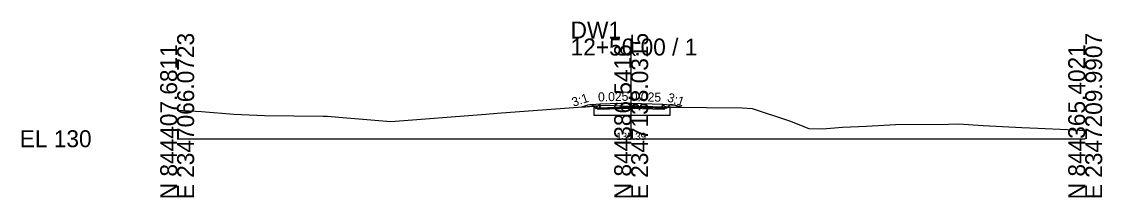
# Model space of a CAD drawing. Extents: x -26 to 2347152, y 490 to 844394.
# Drawn here: x -25.7 to 152.8, y 2490.3 to 2519.3 of the extents above; entities that cross this region are included whole.
import ezdxf

# ---------------------------------------------------------------- set-up
doc = ezdxf.new("R2010")
doc.units = 0
for name, color, linetype in [('Exist Cross Section Cell', 7, 'Continuous'), ('Exist XS Center Line Elevation Label', 7, 'Continuous'), ('Exist XS Ground Line', 7, 'Continuous'), ('Prop CMT Pvmt Course 1', 7, 'Continuous'), ('Prop CMT Pvmt Surface', 7, 'Continuous'), ('Prop CMT Pvmt Surface Shoulder', 7, 'Continuous'), ('Prop CMT Shld Paved Course 1', 7, 'Continuous'), ('Prop CMT Slope Grass', 7, 'Continuous'), ('Prop CMT Subgrade Earthwork', 7, 'Continuous'), ('Prop Road Sect_ Recs - UC Shallow (Outline)', 7, 'Continuous'), ('Prop Road Sect_ Recs - UC Shallow (Pattern)', 7, 'Continuous'), ('Prop XS Earthwork Shape', 7, 'Continuous'), ('Prop XS SE Text', 7, 'Continuous'), ('Prop XS Side Slope Text', 7, 'Continuous')]:
    doc.layers.add(name, color=color, linetype=linetype)

msp = doc.modelspace()

# ---------------------------------------------------------------- linework, layer by layer
at = {"layer": 'Exist Cross Section Cell'}
for p, q in [((75, 2500), (75, 2516.55)), ((0, 2500), (75, 2500)), ((75, 2500), (150, 2500))]:
    msp.add_line(p, q, dxfattribs=at)
at = {"layer": 'Exist XS Ground Line'}
msp.add_lwpolyline([(0, 2504.69), (4.02, 2504.49), (9.34, 2504.03), (14.44, 2503.82), (24.1, 2503.72), (24.86, 2503.71), (26.7, 2503.55), (35.29, 2502.82), (50.97, 2504.04), (52.88, 2504.2), (53.56, 2504.25), (70.72, 2505.52), (75, 2505.39), (76.76, 2505.34), (78.58, 2505.33), (81.53, 2505.23), (93.33, 2505.11), (95, 2504.98), (101.16, 2502.98), (104.35, 2501.71), (106.63, 2501.65), (109.91, 2501.9), (113.9, 2502.07), (118.67, 2502.36), (127.41, 2502.43), (129.09, 2502.45), (133.14, 2502.18), (139.52, 2501.84), (142.17, 2501.75), (147.06, 2501.53), (150, 2501.35)], dxfattribs=at)
at = {"layer": 'Prop CMT Pvmt Course 1'}
for p, q in [((75, 2505.86), (69.8, 2505.73)), ((69.8, 2505.73), (69.8, 2505.48)), ((69.8, 2505.06), (75.01, 2505.19)), ((69.8, 2505.06), (75.01, 2505.19)), ((80.2, 2505.06), (74.98, 2505.19)), ((80.2, 2505.06), (74.98, 2505.19)), ((75, 2505.61), (75, 2505.86)), ((75, 2505.86), (80.2, 2505.73)), ((75, 2505.61), (75, 2505.86)), ((75, 2505.61), (75, 2505.73)), ((75, 2505.73), (75, 2505.73)), ((75, 2505.73), (75, 2505.61)), ((75, 2505.61), (75, 2505.73)), ((75, 2505.73), (75, 2505.73)), ((75, 2505.73), (75, 2505.61)), ((75, 2505.61), (75, 2505.61)), ((75, 2505.61), (75, 2505.61)), ((80.2, 2505.73), (80.2, 2505.48))]:
    msp.add_line(p, q, dxfattribs=at)
for points in [[(75, 2505.86), (69.8, 2505.73)], [(69.8, 2505.73), (69.8, 2505.06)], [(75, 2505.61), (75, 2505.86)], [(75, 2505.86), (80.2, 2505.73)], [(75, 2505.19), (75, 2505.86)], [(80.2, 2505.73), (80.2, 2505.06)]]:
    msp.add_lwpolyline(points, dxfattribs=at)
msp.add_lwpolyline([(75, 2505.61), (75, 2505.73), (75, 2505.73), (75, 2505.61)], close=True, dxfattribs=at)
msp.add_lwpolyline([(75, 2505.61), (75, 2505.73), (75, 2505.73), (75, 2505.61)], close=True, dxfattribs=at)
at = {"layer": 'Prop CMT Pvmt Surface'}
for q in [(69.8, 2505.73), (80.2, 2505.73)]:
    msp.add_line((75, 2505.86), q, dxfattribs=at)
for points in [[(75, 2505.86), (69.8, 2505.73)], [(75, 2505.86), (80.2, 2505.73)]]:
    msp.add_lwpolyline(points, dxfattribs=at)
at = {"layer": 'Prop CMT Pvmt Surface Shoulder'}
for p, q in [((69.8, 2505.73), (69.8, 2505.73)), ((80.2, 2505.73), (80.2, 2505.73))]:
    msp.add_line(p, q, dxfattribs=at)
for points in [[(69.8, 2505.73), (69.8, 2505.73)], [(80.2, 2505.73), (80.2, 2505.73)]]:
    msp.add_lwpolyline(points, dxfattribs=at)
at = {"layer": 'Prop CMT Shld Paved Course 1'}
for p, q in [((69.8, 2505.73), (69.12, 2505.05)), ((69.54, 2505.05), (69.8, 2505.06)), ((69.8, 2505.73), (69.8, 2505.73)), ((69.8, 2505.48), (69.8, 2505.73)), ((80.2, 2505.73), (80.2, 2505.73)), ((80.2, 2505.73), (80.88, 2505.05)), ((80.2, 2505.48), (80.2, 2505.73)), ((80.46, 2505.05), (80.2, 2505.06))]:
    msp.add_line(p, q, dxfattribs=at)
for points in [[(69.8, 2505.73), (69.12, 2505.05)], [(69.12, 2505.05), (69.8, 2505.06)], [(69.8, 2505.73), (69.8, 2505.73)], [(69.8, 2505.06), (69.8, 2505.73)], [(80.2, 2505.73), (80.2, 2505.73)], [(80.2, 2505.73), (80.88, 2505.05)], [(80.2, 2505.06), (80.2, 2505.73)], [(80.88, 2505.05), (80.2, 2505.06)]]:
    msp.add_lwpolyline(points, dxfattribs=at)
at = {"layer": 'Prop CMT Slope Grass'}
for p, q in [((67.8, 2505.57), (66.77, 2505.22)), ((69.8, 2505.73), (67.8, 2505.57)), ((80.2, 2505.73), (82.2, 2505.57)), ((82.2, 2505.57), (83.26, 2505.21))]:
    msp.add_line(p, q, dxfattribs=at)
at = {"layer": 'Prop CMT Subgrade Earthwork'}
for p, q in [((68.54, 2505.63), (69.12, 2505.05)), ((81.46, 2505.63), (80.88, 2505.05))]:
    msp.add_line(p, q, dxfattribs=at)
for points in [[(75.01, 2505.19), (69.12, 2505.05)], [(75.01, 2505.19), (80.88, 2505.05)]]:
    msp.add_lwpolyline(points, dxfattribs=at)
at = {"layer": 'Prop Road Sect_ Recs - UC Shallow (Outline)'}
for p, q in [((69.16, 2505.4), (68.82, 2505.38)), ((68.82, 2505.38), (68.82, 2503.88)), ((69.61, 2504.85), (69.16, 2505.4)), ((75, 2504.98), (69.61, 2504.85)), ((75.01, 2504.98), (71, 2504.88)), ((80.39, 2504.85), (75, 2504.98)), ((80.72, 2505.26), (80.39, 2504.85)), ((81.42, 2505.23), (80.72, 2505.26)), ((81.43, 2503.88), (81.42, 2505.23)), ((68.82, 2503.88), (81.43, 2503.88))]:
    msp.add_line(p, q, dxfattribs=at)
at = {"layer": 'Prop Road Sect_ Recs - UC Shallow (Pattern)'}
msp.add_lwpolyline([(68.82, 2505.38), (68.82, 2503.88), (81.43, 2503.88), (81.42, 2505.23), (80.72, 2505.26), (80.39, 2504.85), (75, 2504.98), (69.61, 2504.85), (69.16, 2505.4), (68.82, 2505.38)], dxfattribs=at)
msp.add_lwpolyline([(68.82, 2505.38), (68.82, 2503.88), (81.43, 2503.88), (81.42, 2505.23), (80.72, 2505.26), (80.39, 2504.85), (75, 2504.98), (69.61, 2504.85), (69.16, 2505.4), (68.82, 2505.38)], dxfattribs=at)
at = {"layer": 'Prop XS Earthwork Shape'}
for points in [[(68.54, 2505.63), (67.8, 2505.57), (66.77, 2505.22), (68.79, 2505.37)], [(81.08, 2505.24), (80.88, 2505.05), (75.01, 2505.19), (69.12, 2505.05), (68.79, 2505.37), (70.72, 2505.52), (75, 2505.39), (76.76, 2505.34), (78.58, 2505.33)], [(81.08, 2505.24), (81.53, 2505.23), (83.26, 2505.21), (82.2, 2505.57), (81.46, 2505.63)]]:
    msp.add_lwpolyline(points, close=True, dxfattribs=at)

# ---------------------------------------------------------------- texts
at = {"layer": 'Exist Cross Section Cell'}
for s, p in [('DW1', (65, 2516.55)), ('12+50.00 / 1', (65, 2513.75)), ('EL 130', (-26, 2498.6))]:
    msp.add_text(s, height=2.8, dxfattribs=at).set_placement(p)
for s, p in [('E 2347066.0723', (2.8, 2490)), ('E 2347138.0315', (77.8, 2490)), ('E 2347209.9907', (152.8, 2490)), ('N 844407.6811', (0, 2490)), ('N 844386.5416', (75, 2490)), ('N 844365.4021', (150, 2490))]:
    msp.add_text(s, height=2.8, rotation=90, dxfattribs=at).set_placement(p)
at = {"layer": 'Exist XS Center Line Elevation Label'}
msp.add_text('135.39', height=1.2, dxfattribs=at).set_placement((72.55, 2499.79))
at = {"layer": 'Prop XS SE Text'}
for rotation, p in [(1.4321, (69.54, 2506.15)), (358.5679, (74.91, 2506.23))]:
    msp.add_text('0.025', height=1.5, rotation=rotation, dxfattribs=at).set_placement(p)
at = {"layer": 'Prop XS Side Slope Text'}
for rotation, p in [(18.4349, (65.47, 2505.26)), (341.5651, (80.84, 2506.21))]:
    msp.add_text('3:1', height=1.5, rotation=rotation, dxfattribs=at).set_placement(p)

doc.saveas('drawing.dxf')
